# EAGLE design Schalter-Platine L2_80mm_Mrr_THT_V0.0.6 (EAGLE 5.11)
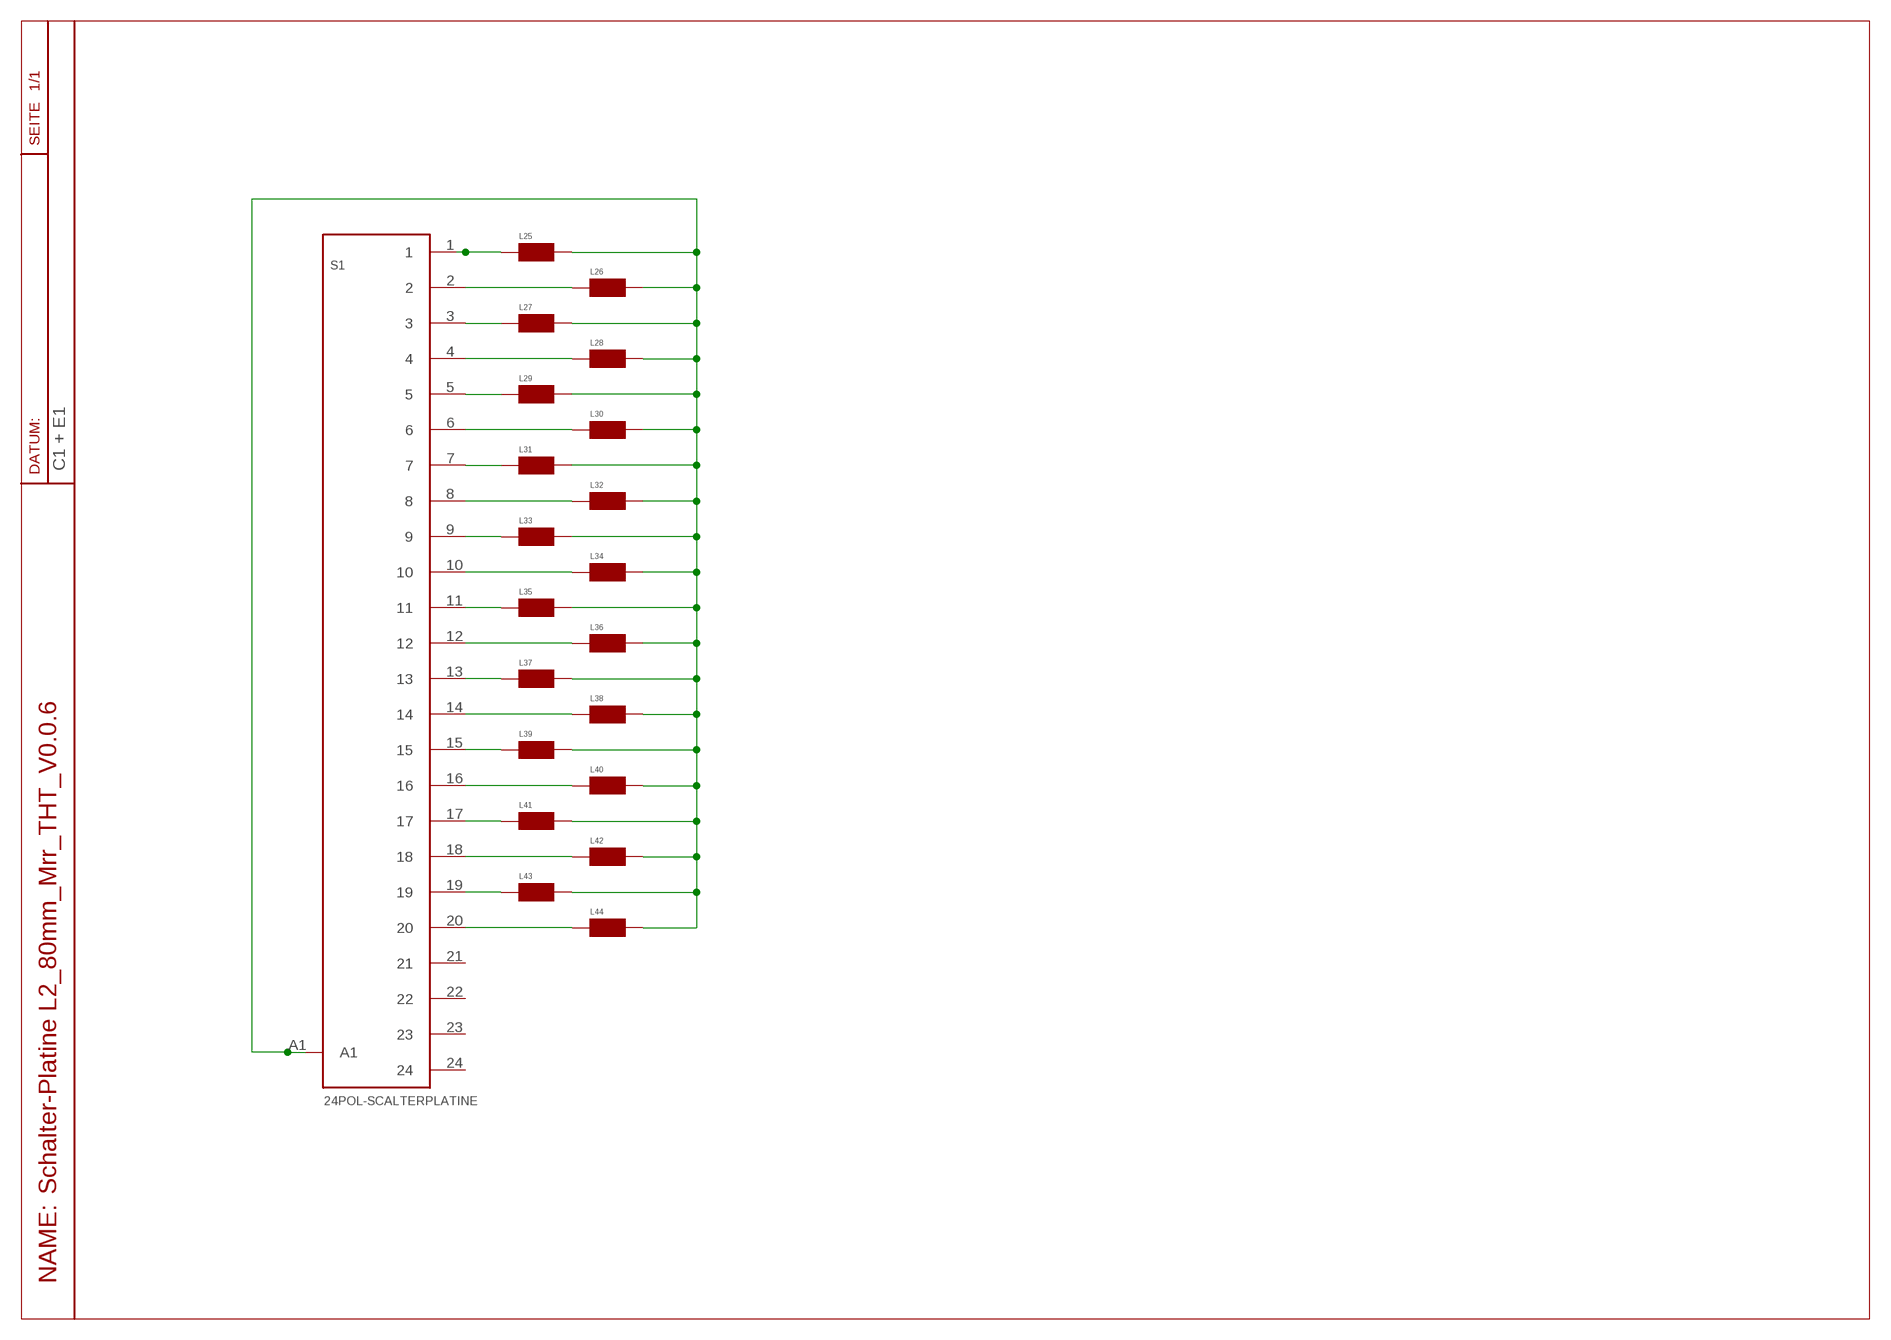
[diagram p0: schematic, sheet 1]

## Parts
L25  L5-9  [L-5-9]
L26  L5-9  [L-5-9]
L27  L5-9  [L-5-9]
L28  L5-9  [L-5-9]
L29  L5-9  [L-5-9]
L30  L5-9  [L-5-9]
L31  L5-9  [L-5-9]
L32  L5-9  [L-5-9]
L33  L5-9  [L-5-9]
L34  L5-9  [L-5-9]
L35  L5-9  [L-5-9]
L36  L5-9  [L-5-9]
L37  L  [L5-12]
L38  L  [L5-12]
L39  L  [L5-12]
L40  L  [L5-12]
L41  L  [L5-12]
L42  L  [L5-12]
L43  L  [L5-12]
L44  L  [L5-12]
S1  24POL-SCALTERPLATINE  24POL-SCALTERPLATINEGROSS  [DREHSCHALTER-GROSS]

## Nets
N$1: L25.2 L26.2 L27.2 L28.2 L29.2 L30.2 L31.2 L32.2 L33.2 L34.2 L35.2 L36.2 L37.2 L38.2 L39.2 L40.2 L41.2 L42.2 L43.2 L44.2 S1.A1
N$2: L25.1 S1.1
N$3: L26.1 S1.2
N$4: L27.1 S1.3
N$5: L28.1 S1.4
N$6: L29.1 S1.5
N$7: L30.1 S1.6
N$8: L31.1 S1.7
N$9: L32.1 S1.8
N$10: L34.1 S1.10
N$11: L33.1 S1.9
N$12: L35.1 S1.11
N$13: L36.1 S1.12
N$14: L37.1 S1.13
N$15: L38.1 S1.14
N$16: L39.1 S1.15
N$17: L40.1 S1.16
N$18: L41.1 S1.17
N$19: L42.1 S1.18
N$20: L43.1 S1.19
N$21: L44.1 S1.20
Unconnected: S1.21 S1.22 S1.23 S1.24

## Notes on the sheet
- C1 + E1

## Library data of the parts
L25-L44 = RLC-BOX:L
S1 = RLC-BOX:24POL-SCALTERPLATINE

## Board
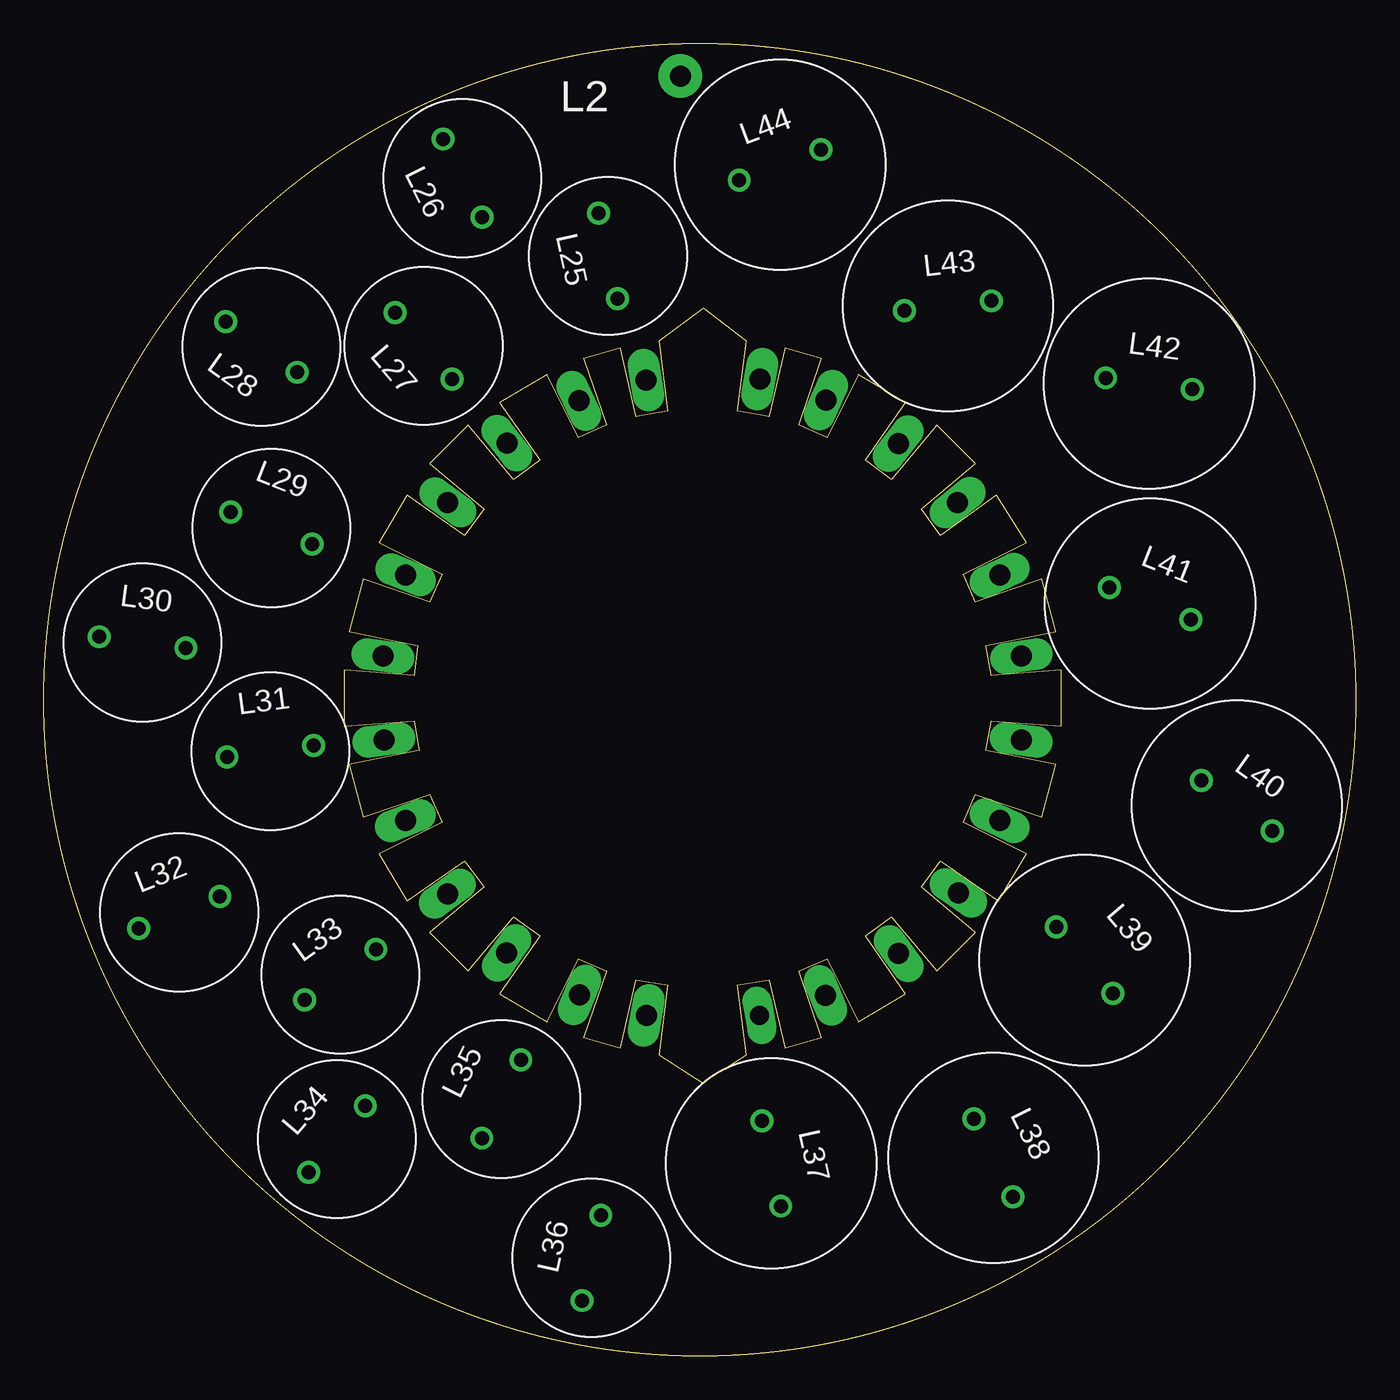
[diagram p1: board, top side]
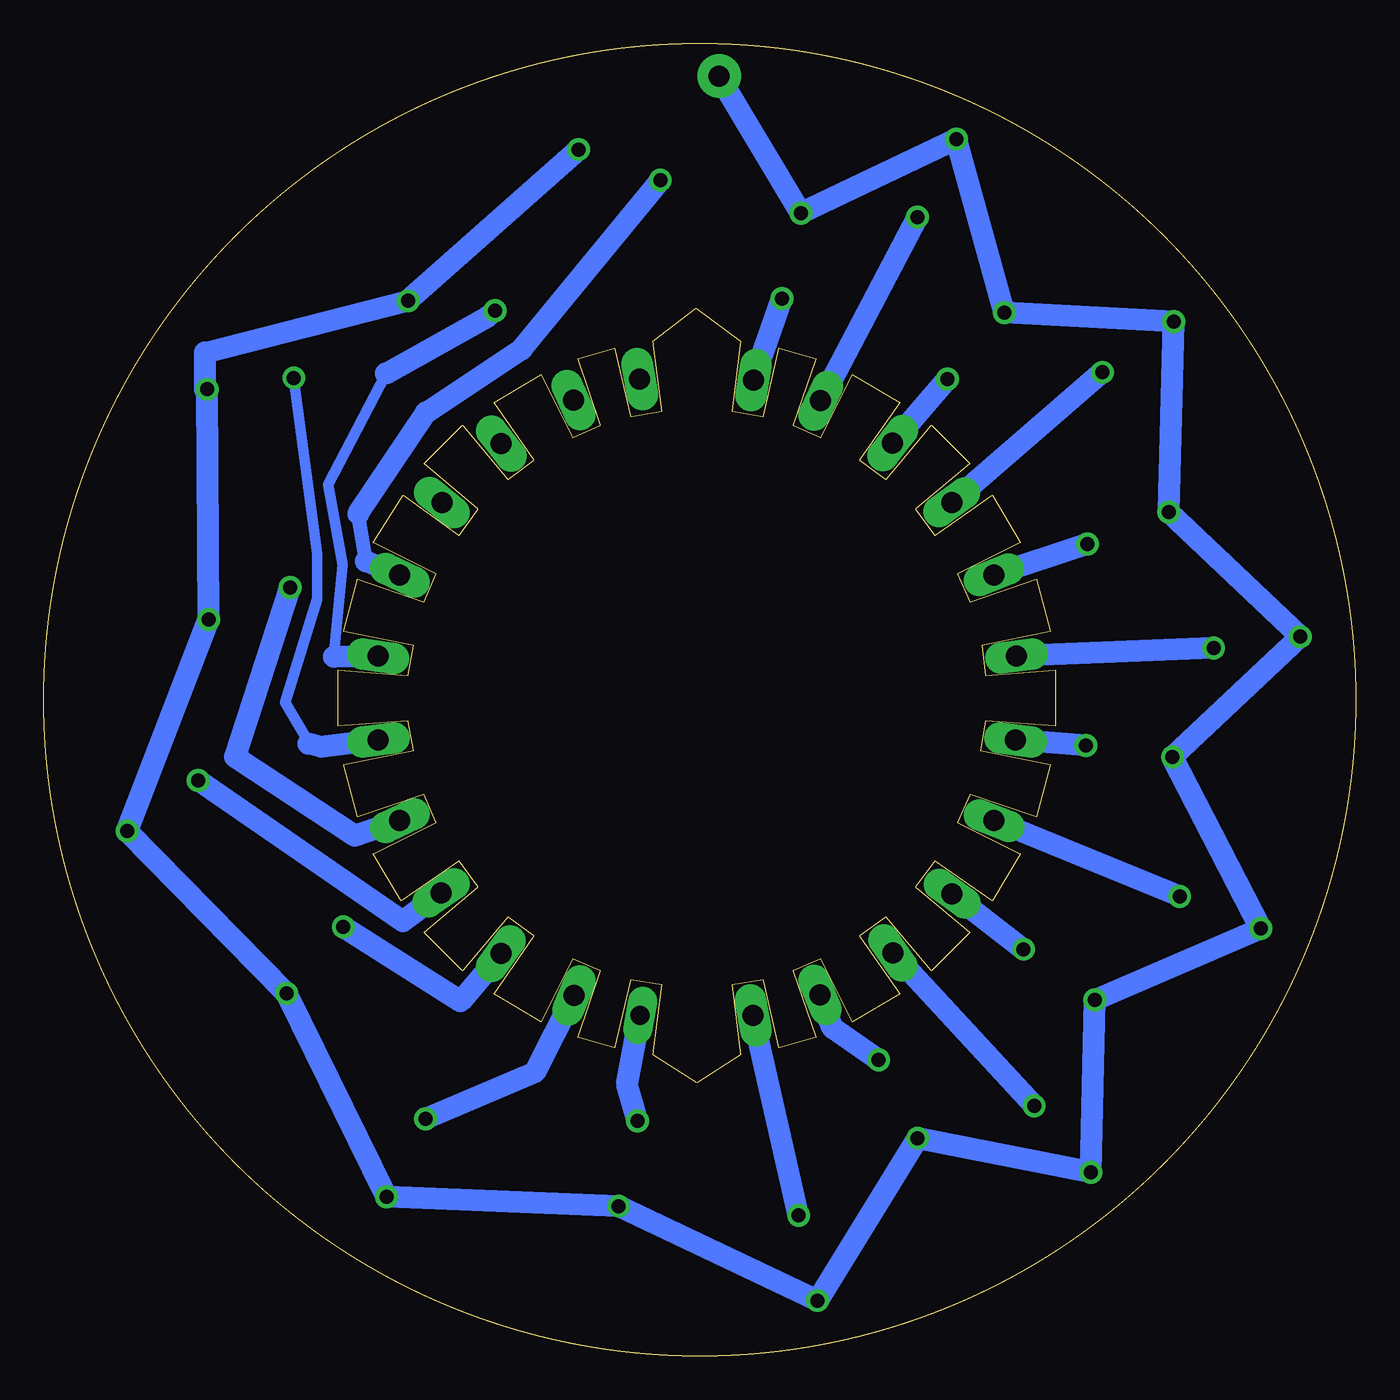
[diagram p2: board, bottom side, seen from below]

Size 75 x 75 mm. Coordinates in mm from the lower left corner, seen from the top.
Outline: circle at 37.5,37.5 radius 37.5
Copper layers (1*16): Top 0.035mm / dielectric 1.5mm / Bottom 0.035mm
Design rules "PCBWay": minimum track width 8mil, minimum drill 0.3mm, track to track 6mil, track to pad 6mil, pad to pad 6mil, via to via 6mil, smd to smd 6mil, copper to edge 40mil, drill to drill 8mil, minimum pad ring 10mil, minimum via ring 8mil, stop-mask expansion 4mil, vias tented up to drill 0mil, thermal gap 20mil

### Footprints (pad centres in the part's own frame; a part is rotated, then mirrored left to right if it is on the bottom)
L-5-9 = drill 0.8 round: 1 -2.5,0; 2 2.5,0
L5-12 = drill 0.8 round: 1 -2.5,0; 2 2.5,0
DREHSCHALTER-GROSS = drill 1.2 pad 1.6 long: 1 3.228,18.163; 2 7.064,16.998; 3 11.181,14.582; 4 14.562,11.184; 5 16.972,7.033; 6 18.265,2.413; 7 18.212,-2.398; 8 16.982,-7.008; 9 14.582,-11.189; 10 11.189,-14.575; 11 7.026,-16.97; 12 3.208,-18.151; 14 -7.025,-16.995; 15 -11.209,-14.607; 16 -14.62,-11.143; 17 -16.99,-7.01; 18 -18.219,-2.395; 19 -18.23,2.39; 20 -16.99,7.023; 21 -14.585,11.181; 22 -11.196,14.554; 23 -7.056,17.026; 24 -3.282,18.225 | drill 1.1 pad 1.6 long: 13 -3.256,-18.141 | drill 1.2 pad 2.5 round: A1 1.27,35.56

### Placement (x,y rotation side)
L25  32.25,62.87 102.5 top
L26  23.94,67.32 116.5 top
L27  21.71,57.73 130.5 top
L28  12.44,57.67 144.5 top
L29  13.01,47.32 158.5 top
L30  5.65,40.78 172.5 top
L31  12.95,34.55 187.5 top
L32  7.74,25.35 201.5 top
L33  16.95,21.79 215.5 top
L34  16.76,12.39 229.5 top
L35  26.16,14.68 243.5 top
L36  31.3,5.6 257.5 top
L37  41.59,11 282.5 top
L38  54.29,11.31 296.5 top
L39  59.5,22.62 310.5 top
L40  68.2,31.44 324.5 top
L41  63.24,43 338.5 top
L42  63.18,55.57 352.5 top
L43  51.69,60.02 6.5 top
L44  42.1,68.08 20.5 top
S1  37.66,37.6 0 bottom

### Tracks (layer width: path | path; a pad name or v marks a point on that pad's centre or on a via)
N$1
  Bottom 1.27: S1.A1 L25.2 L26.2 L27.2 L28.2 L29.2 L30.2 L31.2 L32.2 L33.2 L34.2 L35.2 L36.2 L37.2 L38.2 L39.2 L40.2 L41.2 L42.2 65.78,55.25 65.78,57.35 L43.2 L44.2
N$2
  Bottom 1.27: S1.1 L25.1
N$3
  Bottom 0.406: 30.6,54.53 29.83,55.74 S1.2
  Bottom 1.27: 30.6,54.53 L26.1
N$4
  Bottom 1.27: S1.3 L27.1
N$5
  Bottom 1.27: L28.1 S1.4
N$6
  Bottom 1.27: L29.1 S1.5
N$7
  Bottom 1.27: L30.1 S1.6
N$8
  Bottom 1.27: L31.1 S1.7
N$9
  Bottom 1.27: L32.1 S1.8
N$10
  Bottom 1.27: L34.1 S1.10
N$11
  Bottom 1.27: L33.1 S1.9
N$12
  Bottom 1.27: L35.1 29.91,18.74 S1.11
N$13
  Bottom 1.27: L36.1 S1.12
N$14
  Bottom 1.27: S1.13 41.65,15.5 L37.1
N$15
  Bottom 1.27: S1.14 46.92,16.2 L38.1
N$16
  Bottom 1.27: S1.15 51.18,20.27 L39.1
N$17
  Bottom 1.27: S1.16 54.48,24.84 L40.1
N$18
  Bottom 1.27: S1.17 57.21,29.73 64.07,34.24 L41.1
N$19
  Bottom 0.61: 59.88,35 60,35.32 61.21,37.35 59.37,43.25 59.37,45.86 L42.1
  Bottom 1.27: S1.18 59.12,34.81 59.88,35
N$20
  Bottom 0.61: 58.42,39.95 57.91,45.22 58.73,49.79 55.43,56.14 | 49.65,59.38 L43.1
  Bottom 1.27: S1.19 58.42,39.95 | 55.43,56.14 49.65,59.38
N$21
  Bottom 0.813: 56.58,45.41 57.02,48.14
  Bottom 1.27: S1.20 56.58,45.41 | 57.02,48.14 53.15,53.92 47.69,57.54 L44.1

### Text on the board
tNames: L2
